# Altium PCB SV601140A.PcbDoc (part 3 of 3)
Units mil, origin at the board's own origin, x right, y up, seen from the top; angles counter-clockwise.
Board outline 5208 x 5464 mil, 4 copper layers (Top Layer, MidLayer1, MidLayer2, Bottom Layer), stack 61.2 mil thick; 45 components, 23 nets, 134 pads, 62 vias.
Unrouted connection lines stored in the file: 1.
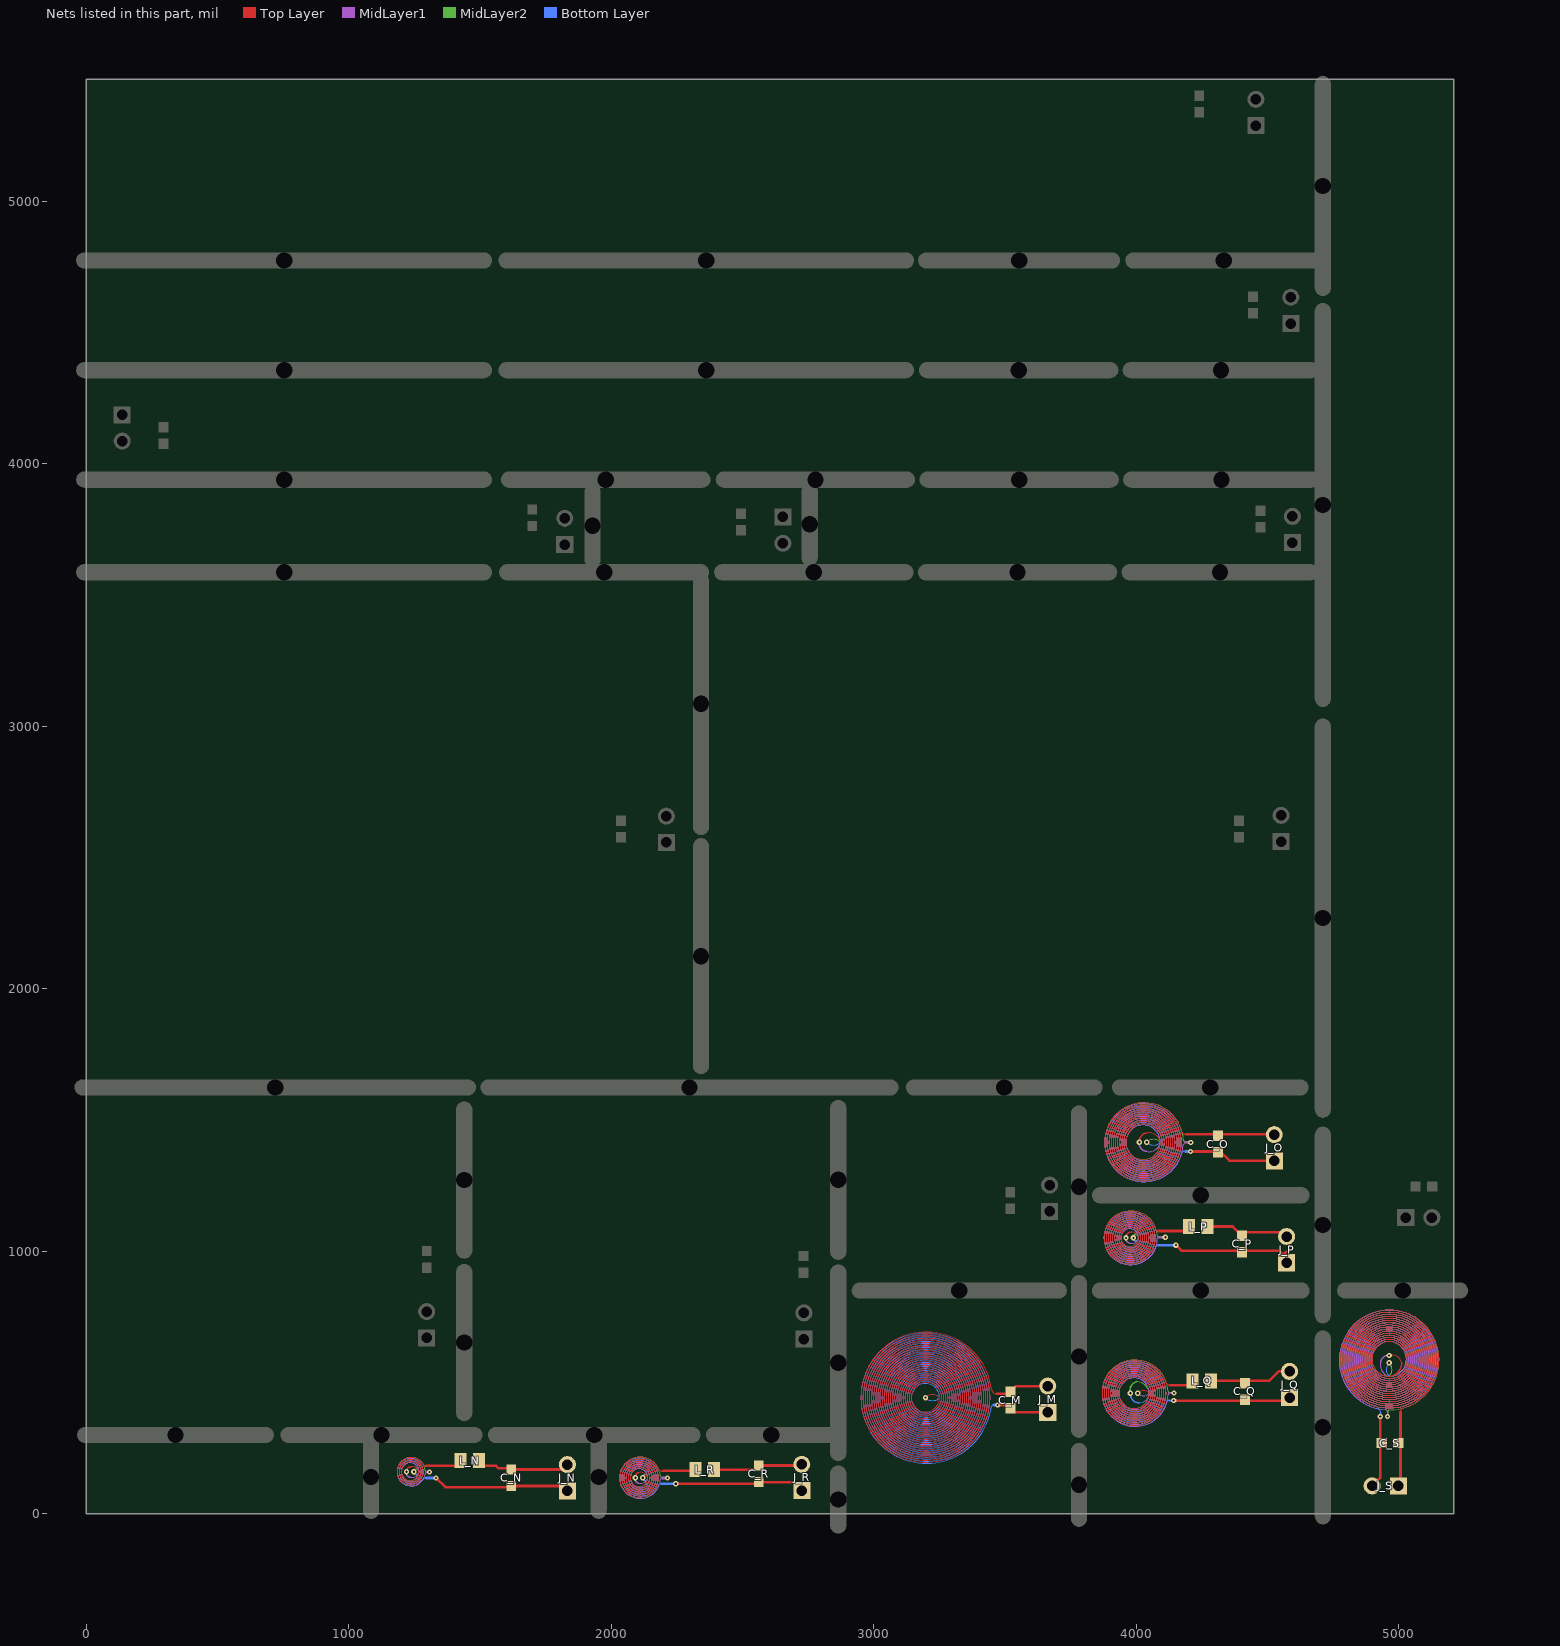
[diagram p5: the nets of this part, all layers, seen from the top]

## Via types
v1: diameter 20, hole 8, Top Layer to Bottom Layer, tented both sides, 49 vias
v2: diameter 46, hole 16, Top Layer to Bottom Layer, tented both sides, 12 vias
v3: diameter 23, hole 8, Top Layer to Bottom Layer, tented both sides, 1 vias

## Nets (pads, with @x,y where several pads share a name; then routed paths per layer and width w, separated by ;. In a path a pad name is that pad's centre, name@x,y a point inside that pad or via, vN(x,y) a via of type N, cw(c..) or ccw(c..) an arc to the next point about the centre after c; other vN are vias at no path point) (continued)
NetC_M_1: C_M.1 C_M.2 J_M.1 J_M.2 | length 48260.8
  Top Layer w4: v1(3196,442) cw(c3223,415) 3250,442 cw(c3196,442) 3142,442 cw(c3200,442) 3258,442 cw(c3196,442) 3134,442 cw(c3200,442) 3266,442 cw(c3196,442) 3126,442 cw(c3200,442) 3274,442 cw(c3196,442) 3118,442 cw(c3200,442) 3282,442 cw(c3196,442) 3110,442 cw(c3200,442) 3290,442 cw(c3196,442) 3102,442 cw(c3200,442) 3298,442 cw(c3196,442) 3094,442 cw(c3200,442) 3306,442 cw(c3196,442) 3086,442 cw(c3200,442) 3314,442 cw(c3196,442) 3078,442 cw(c3200,442) 3322,442 cw(c3196,442) 3070,442 cw(c3200,442) 3330,442 cw(c3196,442) 3062,442 cw(c3200,442) 3338,442 cw(c3196,442) 3054,442 cw(c3200,442) 3346,442 cw(c3196,442) 3046,442 cw(c3200,442) 3354,442 cw(c3196,442) 3038,442 cw(c3200,442) 3362,442 cw(c3196,442) 3030,442 cw(c3200,442) 3370,442 cw(c3196,442) 3022,442 cw(c3200,442) 3378,442 cw(c3196,442) 3014,442 cw(c3200,442) 3386,442 cw(c3196,442) 3006,442 cw(c3200,442) 3394,442 cw(c3196,442) 2998,442 cw(c3200,442) 3402,442 cw(c3196,442) 2990,442 cw(c3200,442) 3410,442 cw(c3196,442) 2982,442 cw(c3200,442) 3418,442 cw(c3196,442) 2974,442 cw(c3200,442) 3426,442 cw(c3196,442) 2966,442 cw(c3200,442) 3434,442 cw(c3196,442) 2958,442 cw(c3200,442) 3442,442 cw(c3196,442) 2950,442 cw(c3200,442) 3448.21,471.9 ccw(c3465.55,474.35) 3468,457
  Top Layer w6: C_M.1@3507.33,414.17 C_M.1@3520,401.5
  Top Layer w10: 3468,457 C_M.2@3512.5,457 ; v1(3471.17,414.17) C_M.1@3507.33,414.17 ; C_M.1@3520,401.5 3535.5,386 J_M.1@3662,386 ; C_M.2@3520,464.5 3541.5,486 J_M.2@3662,486
  Bottom Layer w4: v1(3196,442) ccw(c3223,469) 3250,442 ccw(c3196,442) 3142,442 ccw(c3200,442) 3258,442 ccw(c3196,442) 3134,442 ccw(c3200,442) 3266,442 ccw(c3196,442) 3126,442 ccw(c3200,442) 3274,442 ccw(c3196,442) 3118,442 ccw(c3200,442) 3282,442 ccw(c3196,442) 3110,442 ccw(c3200,442) 3290,442 ccw(c3196,442) 3102,442 ccw(c3200,442) 3298,442 ccw(c3196,442) 3094,442 ccw(c3200,442) 3306,442 ccw(c3196,442) 3086,442 ccw(c3200,442) 3314,442 ccw(c3196,442) 3078,442 ccw(c3200,442) 3322,442 ccw(c3196,442) 3070,442 ccw(c3200,442) 3330,442 ccw(c3196,442) 3062,442 ccw(c3200,442) 3338,442 ccw(c3196,442) 3054,442 ccw(c3200,442) 3346,442 ccw(c3196,442) 3046,442 ccw(c3200,442) 3354,442 ccw(c3196,442) 3038,442 ccw(c3200,442) 3362,442 ccw(c3196,442) 3030,442 ccw(c3200,442) 3370,442 ccw(c3196,442) 3022,442 ccw(c3200,442) 3378,442 ccw(c3196,442) 3014,442 ccw(c3200,442) 3386,442 ccw(c3196,442) 3006,442 ccw(c3200,442) 3394,442 ccw(c3196,442) 2998,442 ccw(c3200,442) 3402,442 ccw(c3196,442) 2990,442 ccw(c3200,442) 3410,442 ccw(c3196,442) 2982,442 ccw(c3200,442) 3418,442 ccw(c3196,442) 2974,442 ccw(c3200,442) 3426,442 ccw(c3196,442) 2966,442 ccw(c3200,442) 3434,442 ccw(c3196,442) 2958,442 ccw(c3200,442) 3442,442 ccw(c3196,442) 2950,442 ccw(c3200,442) 3447.94,410.01 cw(c3454.64,407.48) 3457.17,414.17
  Bottom Layer w10: 3457.17,414.17 v1(3471.17,414.17)
NetC_N_1: C_N.1 J_N.1 L_N.2 | length 4216.5
  Top Layer w4: 1233,178 cw(c1241,152) 1267,160 cw(c1233,160) 1199,160 cw(c1237,160) 1275,160 cw(c1233,160) 1191,160 cw(c1237,160) 1283,160 cw(c1233,160) 1183,160 cw(c1237,160) 1284.48,185.72 ccw(c1291.6,189.12) 1295,182
  Top Layer w6: v1(1219,160) cw(c1235,162) 1233,178
  Top Layer w10: 1295,182 L_N.2@1422.54,182 ; v1(1332,136) 1367,101 1604.5,101 1608,104.5 C_N.1@1620.5,92 ; C_N.1@1618,105.5 1813.5,105.5 J_N.1@1832,87 ; J_N.1@1841.5,105.5 J_N.1@1844,108
  MidLayer1 w4: 1233,139 ccw(c1239.5,166.5) 1267,160 ccw(c1233,160) 1199,160 ccw(c1237,160) 1275,160 ccw(c1233,160) 1191,160 ccw(c1237,160) 1283,160 ccw(c1233,160) 1183,160 ccw(c1237,160) 1290.27,151.12 cw(c1298.57,150.69) v1@1299,159
  MidLayer1 w6: v1(1219,160) ccw(c1236.5,156.5) 1233,139
  MidLayer1 w10: v1@1299,159 v1(1307,159)
  MidLayer2 w4: 1256,170 cw(c1256.5,159.5) 1267,160 cw(c1233,160) 1199,160 cw(c1237,160) 1275,160 cw(c1233,160) 1191,160 cw(c1237,160) 1283,160 cw(c1233,160) 1183,160 cw(c1237,160) 1290.77,164.98 ccw(c1297.87,166.1) v1@1299,159
  MidLayer2 w6: v1(1247,160) cw(c1256.5,160.5) 1256,170
  MidLayer2 w10: v1@1299,159 v1(1307,159)
  Bottom Layer w4: 1257,150 ccw(c1257,160) 1267,160 ccw(c1233,160) 1199,160 ccw(c1237,160) 1275,160 ccw(c1233,160) 1191,160 ccw(c1237,160) 1283,160 ccw(c1233,160) 1183,160 ccw(c1237,160) 1282.52,130.95 cw(c1290.79,127.73) 1294,136
  Bottom Layer w6: v1(1247,160) ccw(c1257,160) 1257,150
  Bottom Layer w10: 1294,136 v1(1332,136)
NetC_N_2: C_N.2 J_N.2 L_N.1 | length 353.1
  Top Layer w10: L_N.1@1513.46,182 1560,182 1568.5,173.5 C_N.2@1618,173.5 ; C_N.2@1618,168.5 1813.5,168.5 J_N.2@1832,187 ; J_N.2@1827.5,191.5 J_N.2@1844,208
NetC_O_1: C_O.1 C_O.2 J_O.1 J_O.2 | length 30885.9
  Top Layer w4: 4038,1450 cw(c4047,1406) 4091,1415 cw(c4025,1415) 3959,1415 cw(c4029,1415) 4099,1415 cw(c4025,1415) 3951,1415 cw(c4029,1415) 4107,1415 cw(c4025,1415) 3943,1415 cw(c4029,1415) 4115,1415 cw(c4025,1415) 3935,1415 cw(c4029,1415) 4123,1415 cw(c4025,1415) 3927,1415 cw(c4029,1415) 4131,1415 cw(c4025,1415) 3919,1415 cw(c4029,1415) 4139,1415 cw(c4025,1415) 3911,1415 cw(c4029,1415) 4147,1415 cw(c4025,1415) 3903,1415 cw(c4029,1415) 4155,1415 cw(c4025,1415) 3895,1415 cw(c4029,1415) 4163,1415 cw(c4025,1415) 3887,1415 cw(c4029,1415) 4171,1415 cw(c4025,1415) 3879,1415 cw(c4029,1415) 4174.1,1453.03 ; 4174.1,1453.02 ccw(c4185.06,1456.96) 4189,1446
  Top Layer w6: v1(4011,1415) cw(c4042,1419) 4038,1450
  Top Layer w10: 4189,1446 C_O.2@4304.5,1446 ; v1(4206,1380) C_O.1@4302.5,1380 ; C_O.1@4317,1382.5 4354.5,1345 J_O.1@4534,1345 ; C_O.2@4317,1445.5 J_O.2@4533.5,1445.5
  MidLayer1 w4: 4038,1380 ccw(c4047,1424) 4091,1415 ccw(c4025,1415) 3959,1415 ccw(c4029,1415) 4099,1415 ccw(c4025,1415) 3951,1415 ccw(c4029,1415) 4107,1415 ccw(c4025,1415) 3943,1415 ccw(c4029,1415) 4115,1415 ccw(c4025,1415) 3935,1415 ccw(c4029,1415) 4123,1415 ccw(c4025,1415) 3927,1415 ccw(c4029,1415) 4131,1415 ccw(c4025,1415) 3919,1415 ccw(c4029,1415) 4139,1415 ccw(c4025,1415) 3911,1415 ccw(c4029,1415) 4147,1415 ccw(c4025,1415) 3903,1415 ccw(c4029,1415) 4155,1415 ccw(c4025,1415) 3895,1415 ccw(c4029,1415) 4163,1415 ccw(c4025,1415) 3887,1415 ccw(c4029,1415) 4171,1415 ccw(c4025,1415) 3879,1415 ccw(c4029,1415) 4178.67,1405.02 cw(c4197.32,1395.34) 4188.36,1414.35
  MidLayer1 w6: v1(4011,1415) ccw(c4042,1411) 4038,1380
  MidLayer1 w10: 4188.36,1414.35 v1(4206.65,1414.35)
  MidLayer2 w4: v1(4039,1415) cw(c4065,1389) 4091,1415 cw(c4025,1415) 3959,1415 cw(c4029,1415) 4099,1415 cw(c4025,1415) 3951,1415 cw(c4029,1415) 4107,1415 cw(c4025,1415) 3943,1415 cw(c4029,1415) 4115,1415 cw(c4025,1415) 3935,1415 cw(c4029,1415) 4123,1415 cw(c4025,1415) 3927,1415 cw(c4029,1415) 4131,1415 cw(c4025,1415) 3919,1415 cw(c4029,1415) 4139,1415 cw(c4025,1415) 3911,1415 cw(c4029,1415) 4147,1415 cw(c4025,1415) 3903,1415 cw(c4029,1415) 4155,1415 cw(c4025,1415) 3895,1415 cw(c4029,1415) 4163,1415 cw(c4025,1415) 3887,1415 cw(c4029,1415) 4171,1415 cw(c4025,1415) 3879,1415 cw(c4029,1415) 4178.73,1423.98 ccw(c4189.68,1425.3) 4191,1414.35
  MidLayer2 w10: 4188.36,1414.35 v1(4206.65,1414.35)
  Bottom Layer w4: v1(4039,1415) ccw(c4065,1441) 4091,1415 ccw(c4025,1415) 3959,1415 ccw(c4029,1415) 4099,1415 ccw(c4025,1415) 3951,1415 ccw(c4029,1415) 4107,1415 ccw(c4025,1415) 3943,1415 ccw(c4029,1415) 4115,1415 ccw(c4025,1415) 3935,1415 ccw(c4029,1415) 4123,1415 ccw(c4025,1415) 3927,1415 ccw(c4029,1415) 4131,1415 ccw(c4025,1415) 3919,1415 ccw(c4029,1415) 4139,1415 ccw(c4025,1415) 3911,1415 ccw(c4029,1415) 4147,1415 ccw(c4025,1415) 3903,1415 ccw(c4029,1415) 4155,1415 ccw(c4025,1415) 3895,1415 ccw(c4029,1415) 4163,1415 ccw(c4025,1415) 3887,1415 ccw(c4029,1415) 4171,1415 ccw(c4025,1415) 3879,1415 ccw(c4029,1415) 4173.08,1373.27 cw(c4183.41,1369.67) 4187,1380
  Bottom Layer w10: 4187,1380 v1@4196,1380
NetC_P_1: C_P.1 J_P.1 L_P.2 | length 16225.6
  Top Layer w4: 3976,1072 cw(c3981.5,1045.5) 4008,1051 cw(c3974,1051) 3940,1051 cw(c3978,1051) 4016,1051 cw(c3974,1051) 3932,1051 cw(c3978,1051) 4024,1051 cw(c3974,1051) 3924,1051 cw(c3978,1051) 4032,1051 cw(c3974,1051) 3916,1051 cw(c3978,1051) 4040,1051 cw(c3974,1051) 3908,1051 cw(c3978,1051) 4048,1051 cw(c3974,1051) 3900,1051 cw(c3978,1051) 4056,1051 cw(c3974,1051) 3892,1051 cw(c3978,1051) 4064,1051 cw(c3974,1051) 3884,1051 cw(c3978,1051) 4072,1051 cw(c3974,1051) 3876,1051 cw(c3978,1051) 4075.73,1080.22 ccw(c4080.97,1082.25) 4083,1077
  Top Layer w6: v1(3960,1051) cw(c3978.5,1053.5) 3976,1072 ; L_P.2@4198.55,1093 L_P.2@4199.54,1093
  Top Layer w10: 4083,1077 L_P.2@4182.55,1077 ; v1(4150,1023) 4171,1002 4542,1002 J_P.1@4572,972 ; 4566,993 4571,998
  MidLayer1 w4: 3976,1030 ccw(c3981.5,1056.5) 4008,1051 ccw(c3974,1051) 3940,1051 ccw(c3978,1051) 4016,1051 ccw(c3974,1051) 3932,1051 ccw(c3978,1051) 4024,1051 ccw(c3974,1051) 3924,1051 ccw(c3978,1051) 4032,1051 ccw(c3974,1051) 3916,1051 ccw(c3978,1051) 4040,1051 ccw(c3974,1051) 3908,1051 ccw(c3978,1051) 4048,1051 ccw(c3974,1051) 3900,1051 ccw(c3978,1051) 4056,1051 ccw(c3974,1051) 3892,1051 ccw(c3978,1051) 4064,1051 ccw(c3974,1051) 3884,1051 ccw(c3978,1051) 4072,1051 ccw(c3974,1051) 3876,1051 ccw(c3978,1051) 4079.92,1047 cw(c4086.96,1045.96) 4088,1053
  MidLayer1 w6: v1(3960,1051) ccw(c3978.5,1048.5) 3976,1030
  MidLayer1 w10: 4088,1053 v1(4110,1053)
  MidLayer2 w4: 3996,1064 cw(c3995.5,1051.5) 4008,1051 cw(c3974,1051) 3940,1051 cw(c3978,1051) 4016,1051 cw(c3974,1051) 3932,1051 cw(c3978,1051) 4024,1051 cw(c3974,1051) 3924,1051 cw(c3978,1051) 4032,1051 cw(c3974,1051) 3916,1051 cw(c3978,1051) 4040,1051 cw(c3974,1051) 3908,1051 cw(c3978,1051) 4048,1051 cw(c3974,1051) 3900,1051 cw(c3978,1051) 4056,1051 cw(c3974,1051) 3892,1051 cw(c3978,1051) 4064,1051 cw(c3974,1051) 3884,1051 cw(c3978,1051) 4072,1051 cw(c3974,1051) 3876,1051 cw(c3978,1051) 4079.76,1057.98 ccw(c4086.37,1059.61) 4088,1053
  MidLayer2 w6: v1(3988,1051) cw(c3998.5,1053.5) 3996,1064
  MidLayer2 w10: 4088,1053 v1(4110,1053)
  Bottom Layer w4: 3996,1039 ccw(c3996,1051) 4008,1051 ccw(c3974,1051) 3940,1051 ccw(c3978,1051) 4016,1051 ccw(c3974,1051) 3932,1051 ccw(c3978,1051) 4024,1051 ccw(c3974,1051) 3924,1051 ccw(c3978,1051) 4032,1051 ccw(c3974,1051) 3916,1051 ccw(c3978,1051) 4040,1051 ccw(c3974,1051) 3908,1051 ccw(c3978,1051) 4048,1051 ccw(c3974,1051) 3900,1051 ccw(c3978,1051) 4056,1051 ccw(c3974,1051) 3892,1051 ccw(c3978,1051) 4064,1051 ccw(c3974,1051) 3884,1051 ccw(c3978,1051) 4072,1051 ccw(c3974,1051) 3876,1051 ccw(c3978,1051) 4074.67,1018.46 cw(c4081.61,1016.06) 4084,1023
  Bottom Layer w6: v1(3988,1051) ccw(c3998,1049) 3996,1039
  Bottom Layer w10: 4084,1023 v1(4150,1023)
NetC_P_2: C_P.2 J_P.2 L_P.1 | length 289.3
  Top Layer w10: L_P.1@4270.43,1094 4367.5,1094 ; 4368.5,1093 4389.5,1072 J_P.2@4552,1072
NetC_Q_1: C_Q.1 J_Q.1 L_Q.2 | length 21689.3
  Top Layer w4: v1(4004.71,459) cw(c4026.71,437) 4048.71,459 cw(c3990.71,459) 3932.71,459 cw(c3994.71,459) 4056.71,459 cw(c3990.71,459) 3924.71,459 cw(c3994.71,459) 4064.71,459 cw(c3990.71,459) 3916.71,459 cw(c3994.71,459) 4072.71,459 cw(c3990.71,459) 3908.71,459 cw(c3994.71,459) 4080.71,459 cw(c3990.71,459) 3900.71,459 cw(c3994.71,459) 4088.71,459 cw(c3990.71,459) 3892.71,459 cw(c3994.71,459) 4096.71,459 cw(c3990.71,459) 3884.71,459 cw(c3994.71,459) 4104.71,459 cw(c3990.71,459) 3876.71,459 cw(c3994.71,459) 4112.71,459 cw(c3990.71,459) 3868.71,459 cw(c3994.71,459) 4112.89,502.7 ccw(c4128.15,504.26) 4129.71,489
  Top Layer w10: 4129.71,489 L_Q.2@4198.25,489 ; v1(4141.71,431) 4576.71,431 4588.71,443 J_Q.1@4584.21,447.5
  MidLayer1 w4: v1(4004.71,459) ccw(c4026.71,481) 4048.71,459 ccw(c3990.71,459) 3932.71,459 ccw(c3994.71,459) 4056.71,459 ccw(c3990.71,459) 3924.71,459 ccw(c3994.71,459) 4064.71,459 ccw(c3990.71,459) 3916.71,459 ccw(c3994.71,459) 4072.71,459 ccw(c3990.71,459) 3908.71,459 ccw(c3994.71,459) 4080.71,459 ccw(c3990.71,459) 3900.71,459 ccw(c3994.71,459) 4088.71,459 ccw(c3990.71,459) 3892.71,459 ccw(c3994.71,459) 4096.71,459 ccw(c3990.71,459) 3884.71,459 ccw(c3994.71,459) 4104.71,459 ccw(c3990.71,459) 3876.71,459 ccw(c3994.71,459) 4112.71,459 ccw(c3990.71,459) 3868.71,459 ccw(c3994.71,459) 4120.57,453.01 cw(c4128.14,452.43) 4128.71,460
  MidLayer1 w6: 4128.71,460 v1(4142.71,460)
  MidLayer2 w4: 3998,502 cw(c4001.86,455.14) 4048.71,459 cw(c3990.71,459) 3932.71,459 cw(c3994.71,459) 4056.71,459 cw(c3990.71,459) 3924.71,459 cw(c3994.71,459) 4064.71,459 cw(c3990.71,459) 3916.71,459 cw(c3994.71,459) 4072.71,459 cw(c3990.71,459) 3908.71,459 cw(c3994.71,459) 4080.71,459 cw(c3990.71,459) 3900.71,459 cw(c3994.71,459) 4088.71,459 cw(c3990.71,459) 3892.71,459 cw(c3994.71,459) 4096.71,459 cw(c3990.71,459) 3884.71,459 cw(c3994.71,459) 4104.71,459 cw(c3990.71,459) 3876.71,459 cw(c3994.71,459) 4112.71,459 cw(c3990.71,459) 3868.71,459 cw(c3994.71,459) 4120.57,464.99 ccw(c4127.14,466.57) 4128.71,460
  MidLayer2 w6: v1(3976.71,459) cw(c4008.86,469.86) 3998,502 ; 4128.71,460 v1(4142.71,460)
  Bottom Layer w4: 4008,422 ccw(c4009.86,460.86) 4048.71,459 ccw(c3990.71,459) 3932.71,459 ccw(c3994.71,459) 4056.71,459 ccw(c3990.71,459) 3924.71,459 ccw(c3994.71,459) 4064.71,459 ccw(c3990.71,459) 3916.71,459 ccw(c3994.71,459) 4072.71,459 ccw(c3990.71,459) 3908.71,459 ccw(c3994.71,459) 4080.71,459 ccw(c3990.71,459) 3900.71,459 ccw(c3994.71,459) 4088.71,459 ccw(c3990.71,459) 3892.71,459 ccw(c3994.71,459) 4096.71,459 ccw(c3990.71,459) 3884.71,459 ccw(c3994.71,459) 4104.71,459 ccw(c3990.71,459) 3876.71,459 ccw(c3994.71,459) 4112.71,459 ccw(c3990.71,459) 3868.71,459 ccw(c3994.71,459) 4116.54,426.84 cw(c4124.21,423.33) 4127.71,431
  Bottom Layer w6: v1(3976.71,459) ccw(c4010.86,456.14) 4008,422 ; 4127.71,431 v1(4141.71,431)
NetC_Q_2: C_Q.2 J_Q.2 L_Q.1 | length 321.9
  Top Layer w10: L_Q.1@4282.18,506 4505.71,506 4542.71,543 J_Q.2@4588.71,543
NetC_R_1: C_R.1 J_R.1 L_R.2 | length 9339.5
  Top Layer w4: 2103,156 cw(c2111.5,128.5) 2139,137 cw(c2105,137) 2071,137 cw(c2109,137) 2147,137 cw(c2105,137) 2063,137 cw(c2109,137) 2155,137 cw(c2105,137) 2055,137 cw(c2109,137) 2163,137 cw(c2105,137) 2047,137 cw(c2109,137) 2171,137 cw(c2105,137) 2039,137 cw(c2109,137) 2179,137 cw(c2105,137) 2031,137 cw(c2109,137) 2179.55,170.26 ccw(c2192.41,175.85) 2198,163
  Top Layer w6: v1(2091,137) cw(c2106.5,140.5) 2103,156
  Top Layer w10: 2198,163 L_R.2@2316.54,163 ; v1(2245,114) 2554.5,114 C_R.1@2561,120.5 2692.5,120.5 J_R.1@2725,88
  MidLayer1 w4: 2103,116 ccw(c2110.5,144.5) 2139,137 ccw(c2105,137) 2071,137 ccw(c2109,137) 2147,137 ccw(c2105,137) 2063,137 ccw(c2109,137) 2155,137 ccw(c2105,137) 2055,137 ccw(c2109,137) 2163,137 ccw(c2105,137) 2047,137 ccw(c2109,137) 2171,137 ccw(c2105,137) 2039,137 ccw(c2109,137) 2179,137 ccw(c2105,137) 2031,137 ccw(c2109,137) 2186.68,129.94 cw(c2193.87,128.81) 2195,136
  MidLayer1 w6: v1(2091,137) ccw(c2107.5,132.5) 2103,116
  MidLayer1 w10: 2195,136 v1(2213,136)
  MidLayer2 w4: 2128,148 cw(c2128,137) 2139,137 cw(c2105,137) 2071,137 cw(c2109,137) 2147,137 cw(c2105,137) 2063,137 cw(c2109,137) 2155,137 cw(c2105,137) 2055,137 cw(c2109,137) 2163,137 cw(c2105,137) 2047,137 cw(c2109,137) 2171,137 cw(c2105,137) 2039,137 cw(c2109,137) 2179,137 cw(c2105,137) 2031,137 cw(c2109,137) 2186.69,143.97 ccw(c2194.83,144.14) 2195,136
  MidLayer2 w6: v1(2119,137) cw(c2129,138) 2128,148
  MidLayer2 w10: 2195,136 v1(2213,136)
  Bottom Layer w4: 2129,126 ccw(c2128.5,136.5) 2139,137 ccw(c2105,137) 2071,137 ccw(c2109,137) 2147,137 ccw(c2105,137) 2063,137 ccw(c2109,137) 2155,137 ccw(c2105,137) 2055,137 ccw(c2109,137) 2163,137 ccw(c2105,137) 2047,137 ccw(c2109,137) 2171,137 ccw(c2105,137) 2039,137 ccw(c2109,137) 2179,137 ccw(c2105,137) 2031,137 ccw(c2109,137) 2181.83,109.07 cw(c2189.38,106.45) 2192,114
  Bottom Layer w6: v1(2119,137) ccw(c2129.5,136.5) 2129,126
  Bottom Layer w10: 2192,114 v1(2245,114)
NetC_R_2: C_R.2 J_R.2 L_R.1 | length 344.8
  Top Layer w10: L_R.1@2388.46,168 2545.5,168 C_R.2@2561,183.5 2720.5,183.5 J_R.2@2725,188
NetC_S_1: C_S.1 C_S.2 J_S.1 J_S.2 | length 52401.7
  Top Layer w4: 4962.7,523 cw(c4962.7,589) 4962.7,655 cw(c4962.7,585) 4962.7,515 cw(c4962.7,589) 4962.7,663 cw(c4962.7,585) 4962.7,507 cw(c4962.7,589) 4962.7,671 cw(c4962.7,585) 4962.7,499 cw(c4962.7,589) 4962.7,679 cw(c4962.7,585) 4962.7,491 cw(c4962.7,589) 4962.7,687 cw(c4962.7,585) 4962.7,483 cw(c4962.7,589) 4962.7,695 cw(c4962.7,585) 4962.7,475 cw(c4962.7,589) 4962.7,703 cw(c4962.7,585) 4962.7,467 cw(c4962.7,589) 4962.7,711 cw(c4962.7,585) 4962.7,459 cw(c4962.7,589) 4962.7,719 cw(c4962.7,585) 4962.7,451 cw(c4962.7,589) 4962.7,727 cw(c4962.7,585) 4962.7,443 cw(c4962.7,589) 4962.7,735 cw(c4962.7,585) 4962.7,435 cw(c4962.7,589) 4962.7,743 cw(c4962.7,585) 4962.7,427 cw(c4962.7,589) 4962.7,751 cw(c4962.7,585) 4962.7,419 cw(c4962.7,589) 4962.7,759 cw(c4962.7,585) 4962.7,411 cw(c4962.7,589) 4962.7,767 cw(c4962.7,585) 4962.7,403 cw(c4962.7,589) 4962.7,775 cw(c4962.7,585) 5014.11,402.09 ccw(c5017.45,390.34) 5005.7,387 ; v1(4962.7,603) cw(c4972.85,565.85) 5010,576
  Top Layer w6: 4962.7,523 ccw(c4959.85,573.15) 5010,576
  Top Layer w10: J_S.2@4897.7,106 4928.7,137 v1(4928.7,370) ; J_S.1@5005.7,106 5005.7,387
  MidLayer1 w4: 4930,576 ccw(c4972.85,565.85) 4962.7,523 ccw(c4962.7,589) 4962.7,655 ccw(c4962.7,585) 4962.7,515 ccw(c4962.7,589) 4962.7,663 ccw(c4962.7,585) 4962.7,507 ccw(c4962.7,589) 4962.7,671 ccw(c4962.7,585) 4962.7,499 ccw(c4962.7,589) 4962.7,679 ccw(c4962.7,585) 4962.7,491 ccw(c4962.7,589) 4962.7,687 ccw(c4962.7,585) 4962.7,483 ccw(c4962.7,589) 4962.7,695 ccw(c4962.7,585) 4962.7,475 ccw(c4962.7,589) 4962.7,703 ccw(c4962.7,585) 4962.7,467 ccw(c4962.7,589) 4962.7,711 ccw(c4962.7,585) 4962.7,459 ccw(c4962.7,589) 4962.7,719 ccw(c4962.7,585) 4962.7,451 ccw(c4962.7,589) 4962.7,727 ccw(c4962.7,585) 4962.7,443 ccw(c4962.7,589) 4962.7,735 ccw(c4962.7,585) 4962.7,435 ccw(c4962.7,589) 4962.7,743 ccw(c4962.7,585) 4962.7,427 ccw(c4962.7,589) 4962.7,751 ccw(c4962.7,585) 4962.7,419 ccw(c4962.7,589) 4962.7,759 ccw(c4962.7,585) 4962.7,411 ccw(c4962.7,589) 4962.7,767 ccw(c4962.7,585) 4962.7,403 ccw(c4962.7,589) 4962.7,775 ccw(c4962.7,585) 4949.66,395.45 cw(c4948.46,387.2) 4956.7,386
  MidLayer1 w6: 4930,576 cw(c4959.85,573.15) v1(4962.7,603) ; v1(4956.7,370) 4956.7,386
  MidLayer2 w4: 4956.7,386 cw(c4966.7,385) 4967.7,395 ; v1(4962.7,575) cw(c4936.7,549) 4962.7,523 cw(c4962.7,589) 4962.7,655 cw(c4962.7,585) 4962.7,515 cw(c4962.7,589) 4962.7,663 cw(c4962.7,585) 4962.7,507 cw(c4962.7,589) 4962.7,671 cw(c4962.7,585) 4962.7,499 cw(c4962.7,589) 4962.7,679 cw(c4962.7,585) 4962.7,491 cw(c4962.7,589) 4962.7,687 cw(c4962.7,585) 4962.7,483 cw(c4962.7,589) 4962.7,695 cw(c4962.7,585) 4962.7,475 cw(c4962.7,589) 4962.7,703 cw(c4962.7,585) 4962.7,467 cw(c4962.7,589) 4962.7,711 cw(c4962.7,585) 4962.7,459 cw(c4962.7,589) 4962.7,719 cw(c4962.7,585) 4962.7,451 cw(c4962.7,589) 4962.7,727 cw(c4962.7,585) 4962.7,443 cw(c4962.7,589) 4962.7,735 cw(c4962.7,585) 4962.7,435 cw(c4962.7,589) 4962.7,743 cw(c4962.7,585) 4962.7,427 cw(c4962.7,589) 4962.7,751 cw(c4962.7,585) 4962.7,419 cw(c4962.7,589) 4962.7,759 cw(c4962.7,585) 4962.7,411 cw(c4962.7,589) 4962.7,767 cw(c4962.7,585) 4962.7,403 cw(c4962.7,589) 4962.7,775 cw(c4962.7,585) 4967.7,395.07
  MidLayer2 w6: v1(4956.7,370) 4956.7,386
  Bottom Layer w4: 4929.7,385 ccw(c4917.94,387.91) 4920.85,399.67 cw(c4962.7,585) 4962.7,775 cw(c4962.7,589) 4962.7,403 cw(c4962.7,585) 4962.7,767 cw(c4962.7,589) 4962.7,411 cw(c4962.7,585) 4962.7,759 cw(c4962.7,589) 4962.7,419 cw(c4962.7,585) 4962.7,751 cw(c4962.7,589) 4962.7,427 cw(c4962.7,585) 4962.7,743 cw(c4962.7,589) 4962.7,435 cw(c4962.7,585) 4962.7,735 cw(c4962.7,589) 4962.7,443 cw(c4962.7,585) 4962.7,727 cw(c4962.7,589) 4962.7,451 cw(c4962.7,585) 4962.7,719 cw(c4962.7,589) 4962.7,459 cw(c4962.7,585) 4962.7,711 cw(c4962.7,589) 4962.7,467 cw(c4962.7,585) 4962.7,703 cw(c4962.7,589) 4962.7,475 cw(c4962.7,585) 4962.7,695 cw(c4962.7,589) 4962.7,483 cw(c4962.7,585) 4962.7,687 cw(c4962.7,589) 4962.7,491 cw(c4962.7,585) 4962.7,679 cw(c4962.7,589) 4962.7,499 cw(c4962.7,585) 4962.7,671 cw(c4962.7,589) 4962.7,507 cw(c4962.7,585) 4962.7,663 cw(c4962.7,589) 4962.7,515 cw(c4962.7,585) 4962.7,655 cw(c4962.7,589) 4962.7,523 cw(c4988.7,549) v1(4962.7,575)
  Bottom Layer w6: v1@4929.7,371 4929.7,385
pads on no net: Logo1.0

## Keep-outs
Keep-Out Layer:
  lines w10: -5,-5 -5,5469 5213,5469 5213,-5 -5,-5
  text ".Layer_Name" at 577,-858.49 h60

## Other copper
Top Layer:
  text ".Layer_Name" at 577,-858.49 h60
Bottom Layer:
  text ".Layer_Name" at 577,-858.49 h60

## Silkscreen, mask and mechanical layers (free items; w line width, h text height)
Top Overlay:
  text "A: 100x15mm, 23 turns, 6mil trace, 6mil space, 4.06mm loop stepping, 4 layers" at 171,4938 h30
  text "B: 100x8mm, 17 turns, 4mil trace, 4mil space, 5.69mm loop stepping, 2 layers" at 419,4535.5 h30
  text "C: 100x8mm, 17 turns, 4mil trace, 4mil space, 5.69mm loop stepping, 2 layers" at 422,4090 h30
  text "E: 11x6mm," at 1993,3839 h30
  text "12 turns" at 1992,3792 h30
  text "4mil trace" at 1989,3747 h30
  text "D: 40x5mm, 11 turns, 4mil trace, 4mil space," at 79,3745 h30
  text "F: 40x5mm, 11 turns, 4mil trace, 4mil space," at 2840,3731 h30
  text "4mil space" at 1989,3700 h30
  text "3.45mm loop stepping, 2 layers" at 77,3685 h30
  text "3.45mm loop stepping, 4 layers" at 2840,3679 h30
  text "4 layers" at 1989,3658.35 h30
  text "H: 46mm, 50 turns, 6mil trace, 6mil space, 2 layers" at 109,1753 h40
  text "I: 46mm, 40 turns, 8mil trace, 6mil space, 4 layers" at 2449,1749 h40
  text "O: 8mm," at 3859,1505 h30
  text "11 turns" at 3858,1457 h30
  text "4mil trace," at 3855,1408 h30
  text "G: 100x10mm, 23 turns, 4mil trace, 4mil space, 4.17mm loop stepping, 2 layers" at 5138.2,1395 h30 r90
  text "4mil space," at 3857,1362 h30
  text "4 layers" at 3857,1312 h30
  text "P: 5mm," at 3867,1070 h30
  text "L: 13mm, 24 turns" at 2942,1054 h30
  text "9 turns" at 3866,1022 h30
  text "4mil trace, 4mil space," at 2934,998 h30
  text "4mil trace," at 3862,977 h30
  text "4 layers" at 2934,938 h30
  text "4mil space, 4 layers" at 3862,929 h30
  text "S: 10mm," at 4780,738 h30
  text "16 turns" at 4780,688 h30
  text "4mil trace," at 4777,639 h30
  text "4mil space" at 4776,586 h30
  text "2 layers" at 4780,533 h30
  text "K: 29mm, 30 turns," at 1487,508 h40
  text "J: 29mm, 35 turns," at 109,497 h40
  text "8mil trace, 6mil space, 4 layers" at 1484,431 h40
  text "6mil trace, 6mil space, 2 layers" at 102,418 h40
  text "M: 13mm, 25 turns" at 2943,305 h30
  text "Q: 6mm, 9 turns" at 3876,284 h30
  text "4mil trace, 4mil space," at 2938,245 h30
  text "4mil trace, 4mil space," at 3873,233 h30
  text "R: 4mm," at 2014,203 h30
  text "2 layers" at 2941,186 h30
  text "4 layers" at 3874,180 h30
  text "6 turns" at 2013,147 h30
  text "N: 3mm, 3 turns" at 1148,107 h30
  text "4mil trace," at 2010,92 h30
  text "4mil trace," at 1151,62 h30
  text "4mil space, 4 layers" at 2014,36 h30
  text "4mil space, 4 layers" at 1151,19 h30
  text ".Layer_Name" at 577,-858.49 h60
Bottom Overlay:
  rectangle: 1268,1804 1568,1904
  text "For evaluation only:" at 2231,3200 h60
  text "not FCC approved for resale." at 2231,3100 h60
  text "MADE IN U.S." at 2235,2918 h60
  text ".CopyrightYear" at 2116,2157 h60
  text "©" at 2241,2153 h105
  text "TEXAS INSTRUMENTS" at 2233,2030 h60
  text ".PCB_Rev" at 1742,1816 h60
  text "-" at 1633,1803.5 h60
  text ".PRJ_Number" at 2234,1804 h60
  text "LDCCOILEVM" at 882.25,98.02 h60
  text ".Layer_Name" at 577,-858.49 h60
Top Paste:
  text ".Layer_Name" at 577,-858.49 h60
Bottom Paste:
  text ".Layer_Name" at 577,-858.49 h60
Top Solder:
  text ".Layer_Name" at 577,-858.49 h60
  text ".Layer_Name" at 577,-858.49 h60
Bottom Solder:
  text ".Layer_Name" at 577,-858.49 h60
Drill Guide:
  text ".Layer_Name" at 577,-858.49 h60
M1 Board Outline:
  the board outline again, w10
  text ".Layer_Name" at 577,-858.49 h60
M2 Board Dimensions:
  rectangle: 124.5,-410.5 499.5,-285.5
  rectangle: -0.5,-285.5 124.5,-160.5
  lines w7: -0.5,-285.5 999.5,-285.5 ; 124.5,-410.5 124.5,-160.5 ; 249.5,-410.5 249.5,-160.5 ; 499.5,-410.5 499.5,-160.5 ; 749.5,-410.5 749.5,-160.5 ; -0.5,-410.5 -0.5,-160.5 999.5,-160.5 999.5,-410.5 -0.5,-410.5
  lines w10: -0.5,-475.5 -0.5,-455.5 ; 59.5,-485.5 -0.5,-465.5 ; 59.5,-445.5 -0.5,-465.5 ; 223.58,-465.5 -0.5,-465.5 ; 775.42,-465.5 999.5,-465.5 ; 939.5,-485.5 999.5,-465.5 ; 939.5,-445.5 999.5,-465.5 ; 999.5,-475.5 999.5,-455.5
  text "1000 (mil)" at 233.58,-501.49 h60
  text ".Layer_Name" at 577,-858.49 h60
M3 3D STEP Top:
  text ".Layer_Name" at 577,-858.49 h60
M4 3D STEP Bottom:
  text ".Layer_Name" at 577,-858.49 h60
M5 Assembly Top:
  lines w10: -292,-930.17 6308,-930.17 ; -292,-726.83 6310,-726.83 ; -292,-523.5 -292,-1133.5 3713,-1133.5 6310,-1133.5 6310,-523.5 -291.5,-523.5 -291.5,-1133.5 1284,-1133.5 ; 2173,-1133.5 2173,-523.5 ; 3440,-726.83 3440,-523.5 ; 4280,-726.83 4280,-523.5 ; 4902,-1140 4902,-937.17
  text "COMPONENTS MARKED 'DNP' SHOULD NOT BE POPULATED." at 1153.5,-318.5 h60
  text "ASSEMBLY VARIANT:" at 1153,-434 h60
  text ".VariantName" at 2189,-434 h60
  text "PCB VIEWED FROM TOP SIDE" at -228.5,-655.67 h60
  text "BOARD #:" at 2248,-655.67 h60
  text ".PRJ_Number" at 2793.5,-655.67 h60
  text "REV:" at 3638,-655.67 h60
  text ".PCB_Rev" at 3929.5,-655.67 h60
  text "SVN REV:" at 4476,-655.67 h60
  text ".VersionControl_RevNumber" at 4982,-655.67 h60
  text "IGNORE ->" at -228.5,-858.49 h60
  text "PLOT NAME =" at -228.5,-1064.34 h60
  text ".plot_File_Name" at 577,-1064.34 h60
  text "GENERATED    :" at 2250,-1064.34 h60
  text ".Print_Date" at 3119.5,-1064.34 h60
  text ".Print_Time" at 3848.5,-1064.34 h60
  text "TEXAS INSTRUMENTS" at 5113,-1064.34 h60
M6 Assembly Bottom:
  lines w10: -292.5,-727.33 6309.5,-727.33 ; -290.5,-930.67 6309.5,-930.67 ; 1115.5,-1140.5 1115.5,-937.67 ; 1737.5,-727.33 1737.5,-524 ; 2577.5,-727.33 2577.5,-524 ; 3844.5,-1134 3844.5,-524 ; 4733.5,-1134 6309,-1134 6309,-524 -292.5,-524 -292.5,-1134 2304.5,-1134 6309.5,-1134 6309.5,-524
  text "COMPONENTS MARKED 'DNP' SHOULD NOT BE POPULATED." at 6102,-318 h60
  text ".VariantName" at 5058,-434 h60
  text "ASSEMBLY VARIANT:" at 6097,-434 h60
  text ".VersionControl_RevNumber" at 1035.5,-656.17 h60
  text "SVN REV:" at 1541.5,-656.17 h60
  text ".PCB_Rev" at 2088,-656.17 h60
  text "REV:" at 2379.5,-656.17 h60
  text ".PRJ_Number" at 3224,-656.17 h60
  text "BOARD #:" at 3769.5,-656.17 h60
  text "PCB VIEWED FROM BOTTOM SIDE" at 6246,-656.17 h60
  text "IGNORE ->" at 2547.85,-858.49 h60
  text "TEXAS INSTRUMENTS" at 904.5,-1064.84 h60
  text ".Print_Time" at 2169,-1064.84 h60
  text ".Print_Date" at 2898,-1064.84 h60
  text "GENERATED    :" at 3767.5,-1064.84 h60
  text ".plot_File_Name" at 5440.5,-1064.84 h60
  text "PLOT NAME =" at 6246,-1064.84 h60
M9 Title Sheet:
  drawing of 57 lines, arcs and shapes, not listed
  text "1" at 739.84,8036.5 h70
  text "2" at 3235.5,8036.5 h70
  text "3" at 5724.84,8036.5 h70
  text "4" at 8231.51,8036.5 h70
  text "5" at 10730.5,8036.5 h70
  text "6" at 13235.5,8036.5 h70
  text "A" at -416.5,6893.5 h70
  text "A" at 14383.5,6893.5 h70
  text "B" at -416.5,4513.5 h70
  text "B" at 14383.5,4513.5 h70
  text "C" at -416.5,2138.5 h70
  text "C" at 14383.5,2138.5 h70
  text "PROJECT TITLE:" at 11343.5,277.5 h45
  text ".PRJ_Title" at 11393.5,144.17 h70
  text "DESIGNED FOR:" at 11343.5,-23.5 h45
  text ".PRJ_Customer" at 11393.5,-163.5 h70
  text "D" at -416.5,-231.5 h70
  text "D" at 14383.5,-231.5 h70
  text "FILE NAME:" at 11343.5,-323.5 h45
  text ".PCB_File_Name_No_Path" at 11393.5,-443.5 h70
  text "Texas Instruments (TI) and/or its licensors do not warrant the accuracy or completeness of this specification" at 6374,-605.34 h45
  text "ENGINEER:" at 11343.5,-613.5 h45
  text "LAYOUT BY:" at 12848.5,-613.5 h45
  text "or any information contained therein. TI and/or its licensors do not warrant that this design will meet" at 6329.01,-718 h45
  text ".PRJ_Engineer" at 11393.5,-768.49 h70
  text ".PCB_Layout" at 12899,-768.49 h70
  text "the specifications, will be suitable for your application or fit for any particular purpose, or will operate in" at 6329.01,-830.67 h45
  text ".Layer_Name" at 577,-858.49 h60
  text "ALTIUM DESIGNER VERSION:" at 12848.5,-923.5 h45
  text "an implementation. TI and/or its licensors do not warrant that the design is production worthy. You should" at 6329.01,-943.33 h45
  text "completely validate and test your design implementation to confirm the system functionality for your application." at 6374,-1056 h45
  text ".print_Scale" at 11393.5,-1056.83 h70
  text ".Application_BuildNumber" at 12899,-1056.83 h70
  text "1" at 739.84,-1263.5 h70
  text "2" at 3235.5,-1263.5 h70
  text "3" at 5724.84,-1263.5 h70
  text "4" at 8231.51,-1263.5 h70
  text "5" at 10730.5,-1263.5 h70
  text "6" at 13235.5,-1263.5 h70
M10 Fab Notes:
  drawing of 212 lines, arcs and shapes, not listed
  text "DESIGN INFORMATION" at 12381.02,6810 h60
  text "(REFER ALSO ARRAY/PANEL PROFILING INFORMATION)" at 12019.46,6648.29 h60
  text "BOARD SIZE" at 11333.46,6644 h60
  text "5208MIL" at 11795.78,6516.18 h60
  text "X" at 12301.46,6516.18 h60
  text "5464MIL" at 12532.78,6516.18 h60
  text "Number of Layers :" at 11736.46,6319 h60
  text "4" at 12831.27,6309 h60
  text "MIN. TRACK WIDTH:" at 11736.46,6180 h60
  text "4" at 12832.7,6180 h60
  text "MIL" at 12987.46,6180 h60
  text "MIN. CLEARANCE:" at 11736.46,6048 h60
  text "4" at 12832.7,6048 h60
  text "MIL" at 12987.46,6048 h60
  text "MIN. VIA PAD SIZE:" at 11736.46,5916 h60
  text "20" at 12802.71,5916 h60
  text "MIL" at 12987.46,5916 h60
  text "0.05mm (2MIL)" at 12431.46,5774.29 h60
  text "MINIMUM ANNULAR RING" at 11407.23,5770 h60
  text "EXTERNAL" at 13139.46,5770 h60
  text "PER" at 11607.23,5652 h60
  text "IPC-D-275 CLASS 2 LEVEL C" at 11827.23,5652 h60
  text "MIL, HOLES" at 13315.46,5539.71 h60
  text "+/-" at 12923,5539 h60
  text "+/-" at 13777,5539 h60
  text "REGISTRATION TOLERANCES:" at 11407.23,5534 h60
  text "METAL" at 12607,5534 h60
  text "5" at 13183.2,5534 h60
  text "3" at 14016.2,5534 h60
  text "MIL" at 14132.46,5534 h60
  text "MATERIAL:" at 11332.46,5324.54 h60
  text "FR-4 High Tg" at 12318.9,5184.21 h60
  text "FR-408" at 11753.46,5175.64 h60
  text "X" at 12165.46,5175.64 h60
  text "OTHER" at 13241.46,5175.64 h60
  text "62 MIL (1.6mm) +/-10%" at 12073.56,5012.92 h60
  text "THICKNESS:" at 11407.23,5008.64 h60
  text "X" at 11945.4,5008.64 h60
  text "OTHER" at 13358.46,5008.64 h60
  text "TOLERANCE:" at 11407.23,4850.64 h60
  text "X" at 12246.53,4850.64 h60
  text "ANSI IPC-6012 TYPE 3 CLASS 2" at 12433.48,4850.64 h60
  text "OTHER +/-" at 12433.46,4694.64 h60
  text "BOW & TWIST:" at 11407.23,4537.64 h60
  text "X" at 12246.53,4537.64 h60
  text "ANSI IPC-6012 TYPE 3 CLASS 2" at 12433.48,4537.64 h60
  text "OTHER +/-" at 12433.46,4379.13 h60
  text "COPPER THICKNESS (FINISHED):" at 11332.46,4243.64 h60
  text "1.4MIL (1oz)" at 12212.46,4090.92 h60
  text "2MIL (1.4oz)" at 12979.46,4090.92 h60
  text "2.8MIL (2oz)" at 13706.46,4090.92 h60
  text "OUTER:" at 11689.46,4086.64 h60
  text "X" at 12084,4086 h60
  text "1.4MIL (1oz)" at 12212.46,3933.92 h60
  text "2.8MIL (2oz)" at 12979.46,3933.92 h60
  text "N/A" at 13706,3934.29 h60
  text "INNER SIGNAL:" at 11400.38,3929.64 h60
  text "X" at 12085.42,3929.64 h60
  text "DRILLING:" at 11332.46,3790.64 h60
  text "REFERENCE:" at 11407.23,3673.64 h60
  text "X" at 12055.46,3673.64 h60
  text "AS SHOWN" at 12242.46,3673.64 h60
  text "X" at 12956.46,3673.64 h60
  text "NC_DRILL FILES" at 13093.46,3673.64 h60
  text "PTH MIN COPPER THICKNESS:" at 11407.23,3515.64 h60
  text "X" at 12757.46,3515.64 h60
  text "1MIL" at 12894.46,3515.64 h60
  text "OTHER" at 13391.46,3515.64 h60
  text "BOARD FINISH:" at 11332.46,3356.64 h60
  text "SILKSCREEN:" at 11487.68,3238.64 h60
  text "X" at 12436.46,3238.64 h60
  text "TOP" at 12562.46,3238.64 h60
  text "X" at 12946.46,3238.64 h60
  text "BOTTOM" at 13073.46,3238.64 h60
  text "SILKSCREEN COLOR:" at 11487.68,3071.64 h60
  text "X" at 12435.42,3071.64 h60
  text "WHITE" at 12562.46,3071.64 h60
  text "OTHER" at 13073.46,3071.64 h60
  text "SOLDER RESIST COLOR:" at 11487.68,2901.64 h60
  text "X" at 12055.42,2742.44 h60
  text "GREEN" at 12182.46,2742.44 h60
  text "BLUE" at 12773.46,2742.44 h60
  text "OTHER" at 13311.46,2742.44 h60
  text "IMMERSION GOLD (ENIG)" at 12393.46,2553.92 h60
  text "ENEPIG" at 13731,2550.64 h60
  text "SURFACE FINISH:" at 11332.46,2549.64 h60
  text "X" at 12206.51,2549.64 h60
  text "IMM. TIN/SILVER OR EQUIV" at 11662,2392.64 h60
  text "OTHER" at 13093.46,2392.64 h60
  text "ARRAY/PANEL:" at 11332.46,2213.64 h60
  text "CUT AND TRIM PER MECH LAYER 1" at 12393.46,2209.35 h60
  text "N.C. ROUTE" at 12393.46,2057.64 h60
  text "X" at 13072.46,2057.64 h60
  text "V. SCORE" at 13259.46,2057.64 h60
  text "CERTIFICATION:" at 11332.46,1920.64 h60
  text "MATERIALS AND WORKMANSHIP FOR ALL PCBS" at 12057.46,1920.64 h60
  text "TO MEET OR EXCEED THE REQUIREMENTS OF:" at 12057.46,1822.64 h60
  text "X" at 11683.96,1686.13 h60
  text "ANSI IPC-A-600F CLASS ->" at 11822.96,1686.13 h60
  text "X" at 13462.02,1686.13 h60
  text "2" at 13580.96,1686.14 h60
  text "1" at 13265.96,1684.64 h60
  text "3" at 13934.96,1684.64 h60
  text "X" at 11686.02,1526.64 h60
  text "UL 94V-0" at 11822.96,1526.64 h60
  text "X" at 12498.02,1526.64 h60
  text "RoHS" at 12634.96,1526.64 h60
  text "OTHER" at 13279.36,1526.64 h60
  text "PER ORDER" at 13676.42,1526.64 h60
  text "ADDITIONAL REQUIREMENTS:" at 11332.46,1385.64 h60
  text "MICROSECTION:" at 11407.23,1270.64 h60
  text "YES" at 12312.96,1270.64 h60
  text "REQUIRED" at 13174.46,1114.49 h60
  text "BARE BOARD ELEC. TEST:" at 11407.23,1111.64 h60
  text "NONE" at 12712.96,1111.64 h60
  text "X" at 13047.46,1111.64 h60
  text "PER ORDER" at 13766.46,1111.64 h60
  text "MANUFACTURER'S UL:" at 11407.23,954.64 h60
  text "RAIL" at 12572.96,950.35 h60
  text "METAL" at 13064.77,950.35 h60
  text "X" at 13440,950 h60
  text "SILK" at 13576.46,950.35 h60
  text ".Layer_Name" at 577,-858.49 h60
M11 Gerber Information:
  lines w10: -292,-930.17 6308,-930.17 ; -292,-726.83 6310,-726.83 ; -292,-523.5 -292,-1133.5 3713,-1133.5 6310,-1133.5 6310,-523.5 -291.5,-523.5 -291.5,-1133.5 1284,-1133.5 ; 2173,-1133.5 2173,-523.5 ; 3440,-726.83 3440,-523.5 ; 4280,-726.83 4280,-523.5 ; 4902,-1140 4902,-937.17
  text "ALL ARTWORK VIEWED FROM TOP SIDE" at -228.5,-655.67 h60
  text "BOARD #:" at 2248,-655.67 h60
  text ".PRJ_Number" at 2793.5,-655.67 h60
  text "REV:" at 3638,-655.67 h60
  text ".PCB_Rev" at 3929.5,-655.67 h60
  text "SVN REV:" at 4476,-655.67 h60
  text ".VersionControl_RevNumber" at 4982,-655.67 h60
  text "LAYER NAME =" at -228.5,-858.49 h60
  text "PLOT NAME =" at -228.5,-1064.34 h60
  text ".plot_File_Name" at 577,-1064.34 h60
  text "GENERATED    :" at 2250,-1064.34 h60
  text ".Print_Date" at 3119.5,-1064.34 h60
  text ".Print_Time" at 3848.5,-1064.34 h60
  text "TEXAS INSTRUMENTS" at 5113,-1064.34 h60
M12 Stackup:
  lines w5: 11274,7001 ccw(c11305,7001) 11305,6970 14165,6970 ccw(c14165,7001) 14196,7001 14196,7802 ccw(c14165,7802) 14165,7833 11305,7833 ccw(c11305,7802) 11274,7802 11274,7001
  lines w6: 11313,7617.25 14178,7617.25 ; 11313,7729.85 14178,7729.85
  text "Layer Stack Up Detail for: SV601140A.PcbDoc" at 11334,7740.48 h45
  text "Layer" at 11313,7687.85 h26
  text "Gerber" at 12020.2,7687.85 h26
  text "Copper" at 12381.65,7687.85 h26
  text "Dielectric" at 12785.55,7687.85 h26
  text "Dielectric" at 13207.64,7687.85 h26
  text "Dielectric" at 13734.9,7687.85 h26
  text "Name" at 11313,7635.85 h26
  text "Document" at 12020.2,7635.85 h26
  text "Thickness" at 12381.65,7635.85 h26
  text "Height" at 12785.55,7635.85 h26
  text "Material" at 13207.64,7635.85 h26
  text "Type" at 13734.9,7635.85 h26
  text "Top Solder Mask" at 11313,7558.68 h36
  text "(.GTS)" at 12020.2,7558.68 h36
  text "0.4mil" at 12785.55,7558.68 h36
  text "Solder Resist" at 13207.64,7558.68 h36
  text "Top Layer" at 11313,7447.53 h36
  text "(.GTL)" at 12020.2,7447.53 h36
  text "1.4mil" at 12381.65,7447.53 h36
  text "12.6mil" at 12785.55,7391.96 h36
  text "FR-4" at 13207.64,7391.96 h36
  text "Core" at 13734.9,7391.96 h36
  text "MidLayer1" at 11313,7336.39 h36
  text "(.G1)" at 12020.2,7336.39 h36
  text "1.4mil" at 12381.65,7336.39 h36
  text "30.4mil" at 12785.55,7280.81 h36
  text "FR-4" at 13207.64,7280.81 h36
  text "PrePreg" at 13734.9,7280.81 h36
  text "MidLayer2" at 11313,7225.24 h36
  text "(.G2)" at 12020.2,7225.24 h36
  text "1.4mil" at 12381.65,7225.24 h36
  text "12.6mil" at 12785.55,7169.67 h36
  text "FR-4" at 13207.64,7169.67 h36
  text "Core" at 13734.9,7169.67 h36
  text "Bottom Layer" at 11313,7114.09 h36
  text "(.GBL)" at 12020.2,7114.09 h36
  text "1.4mil" at 12381.65,7114.09 h36
  text "Bottom Solder Mask" at 11313,7002.95 h36
  text "(.GBS)" at 12020.2,7002.95 h36
  text "0.4mil" at 12785.55,7002.95 h36
  text "Solder Resist" at 13207.64,7002.95 h36
  text ".Layer_Name" at 577,-858.49 h60
M13 Component Bodies Top:
  text ".Layer_Name" at 577,-858.49 h60
M14 Component Bodies Bottom:
  text ".Layer_Name" at 577,-858.49 h60
M15 Courtyards Top:
  text ".Layer_Name" at 577,-858.49 h60
M16 Courtyards Bottom:
  text ".Layer_Name" at 577,-858.49 h60
Drill Drawing:
  text ".legend" at 5585,60 h40
  text ".Layer_Name" at 577,-858.49 h60

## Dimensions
0,0 to 0,5464 on M2 Board Dimensions
0,0 to 5208,0 on M2 Board Dimensions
